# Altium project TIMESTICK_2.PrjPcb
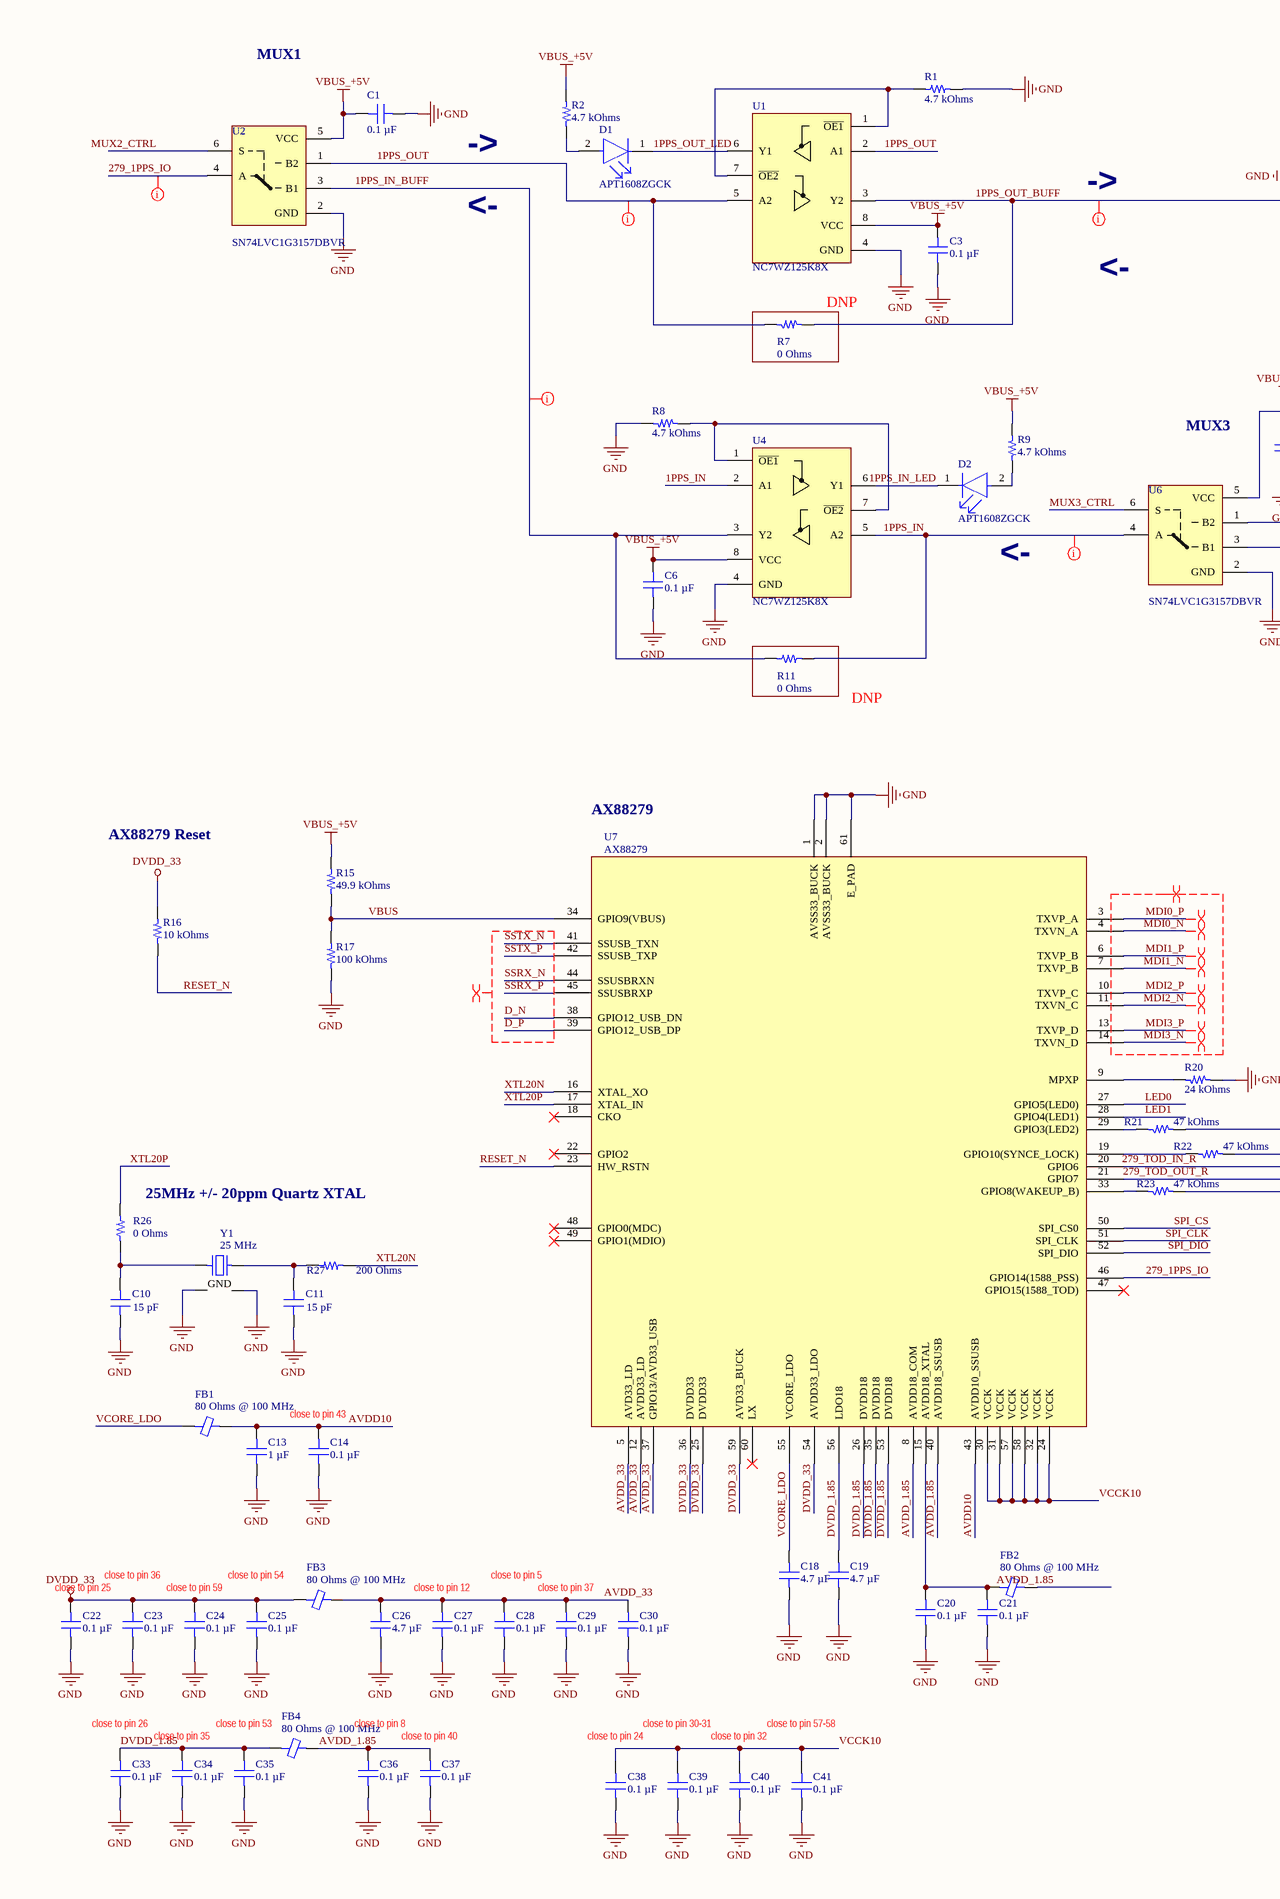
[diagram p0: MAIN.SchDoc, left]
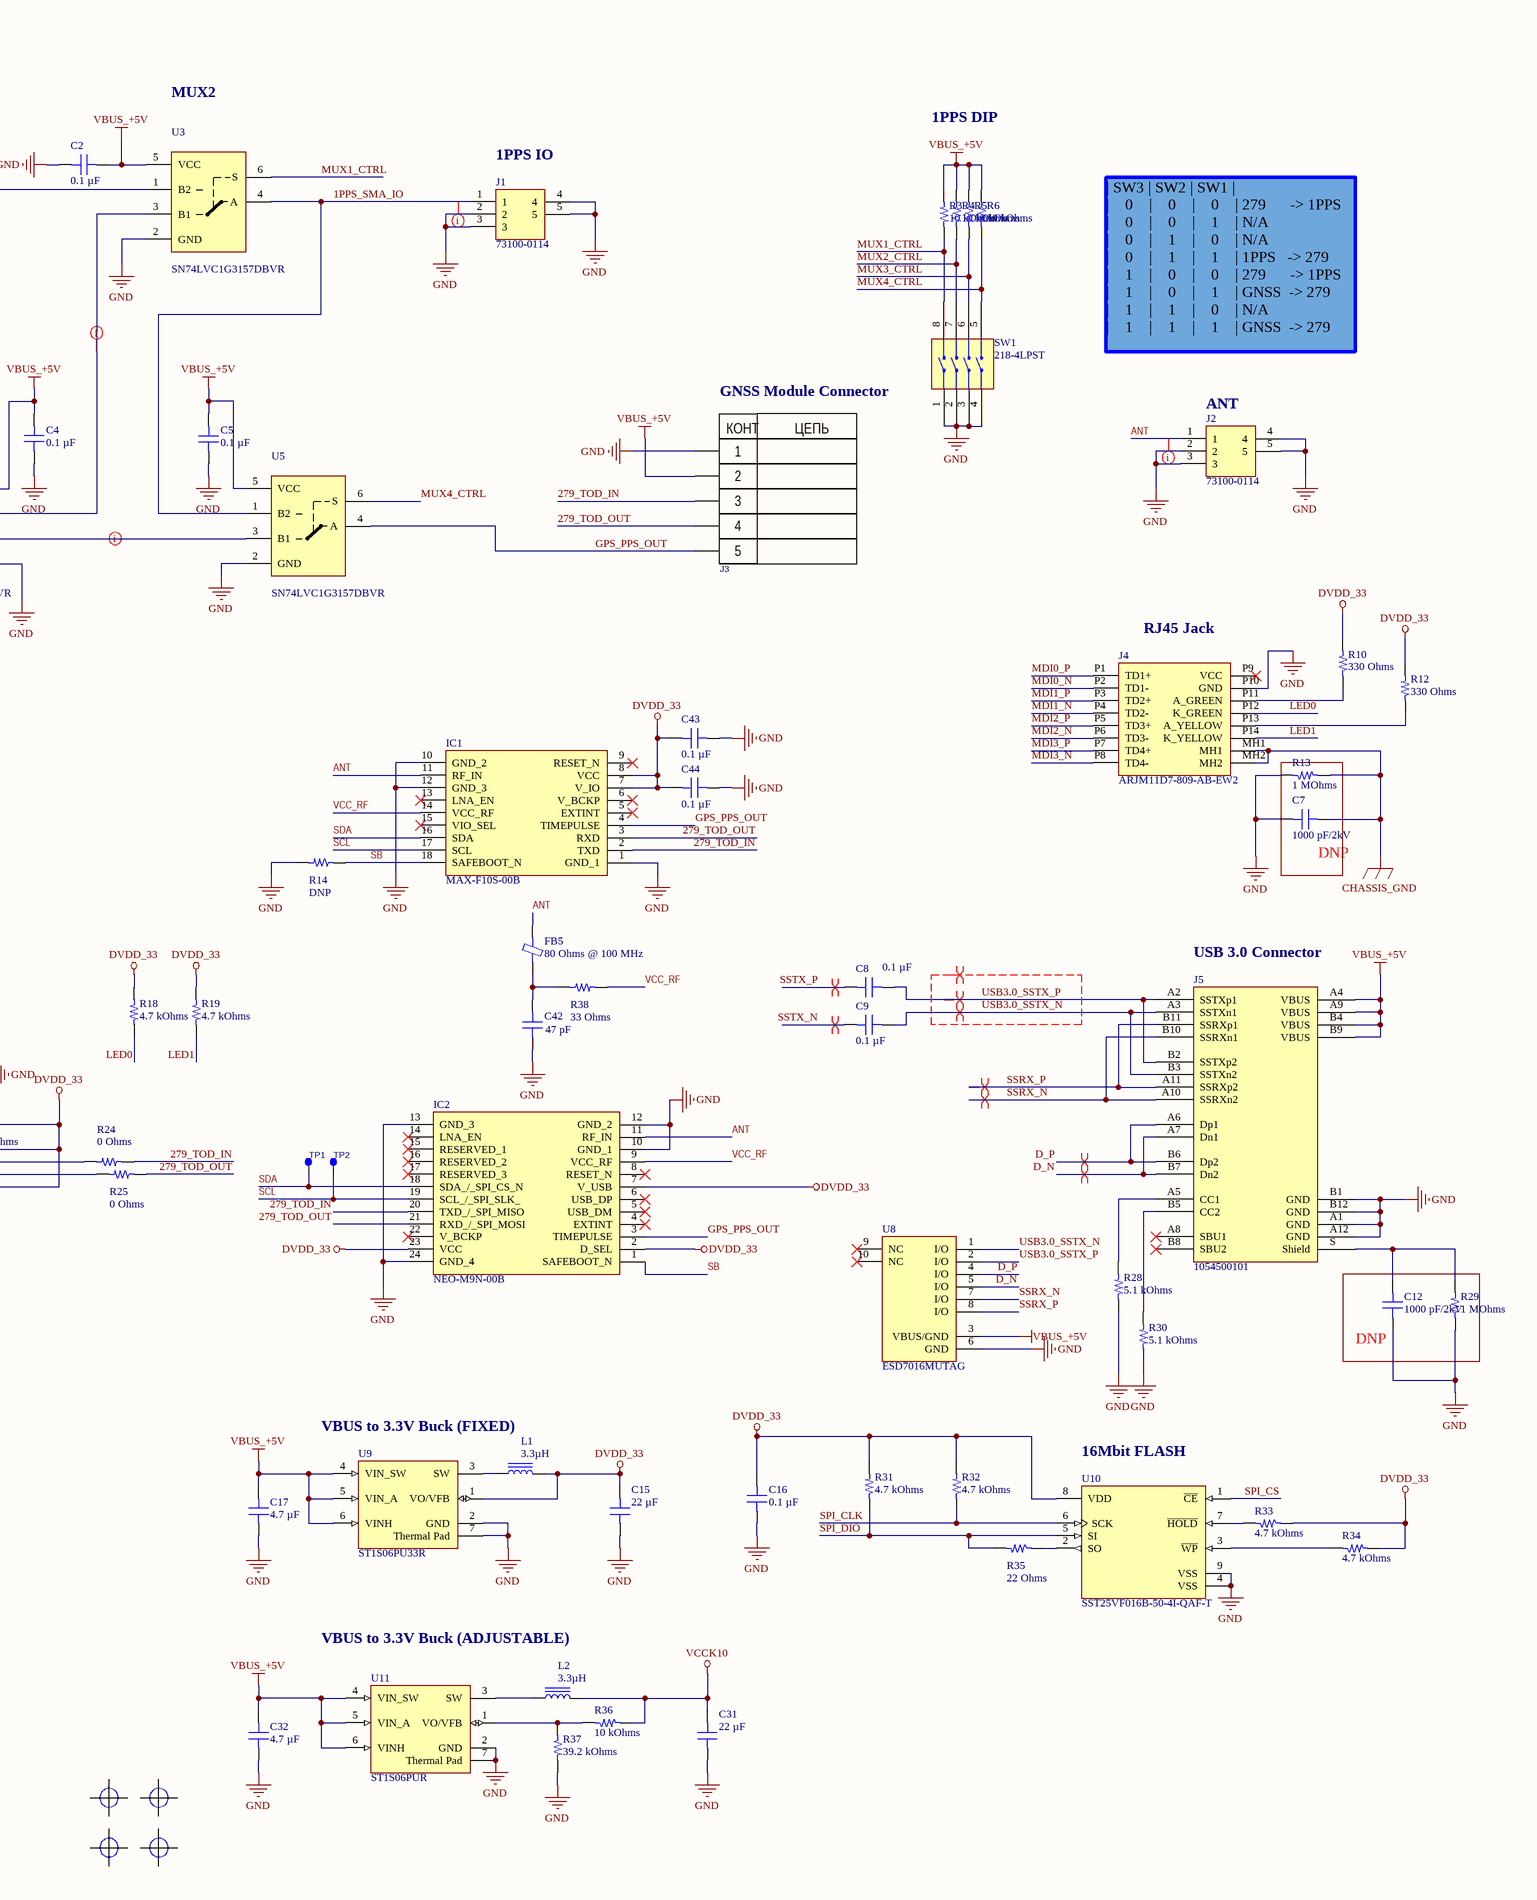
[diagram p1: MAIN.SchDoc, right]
1 sheet, 117 parts. Net scope: global (net labels, ports and power ports of the same name join across sheets).
Board file: TIMESTICK_2.PcbDoc

## Sheet MAIN.SchDoc
size A2; SheetNumber: 1; SheetTotal: 1

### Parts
C1  0.1 µF  [CAP 0402_1005]
C2  0.1 µF  [CAP 0402_1005]
C3  0.1 µF  [CAP 0402_1005]
C4  0.1 µF  [CAP 0402_1005]
C5  0.1 µF  [CAP 0402_1005]
C6  0.1 µF  [CAP 0402_1005]
C7  1000 pF/2kV  [CAP 1206_3216 - 0.8MM]
C8  0.1 µF  [CAP 0402_1005]
C9  0.1 µF  [CAP 0402_1005]
C10  15 pF  [CAP 0402_1005]
C11  15 pF  [CAP 0402_1005]
C12  1000 pF/2kV  [CAP 1206_3216 - 0.8MM]
C13  1 µF  [CAP 0402_1005]
C14  0.1 µF  [CAP 0402_1005]
C15  22 µF  [CAP 0603_1608]
C16  0.1 µF  [CAP 0402_1005]
C17  4.7 µF  [CAP 0402_1005]
C18  4.7 µF  [CAP 0402_1005]
C19  4.7 µF  [CAP 0402_1005]
C20  0.1 µF  [CAP 0402_1005]
C21  0.1 µF  [CAP 0402_1005]
C22  0.1 µF  [CAP 0402_1005]
C23  0.1 µF  [CAP 0402_1005]
C24  0.1 µF  [CAP 0402_1005]
C25  0.1 µF  [CAP 0402_1005]
C26  4.7 µF  [CAP 0402_1005]
C27  0.1 µF  [CAP 0402_1005]
C28  0.1 µF  [CAP 0402_1005]
C29  0.1 µF  [CAP 0402_1005]
C30  0.1 µF  [CAP 0402_1005]
C31  22 µF  [CAP 0603_1608]
C32  4.7 µF  [CAP 0402_1005]
C33  0.1 µF  [CAP 0402_1005]
C34  0.1 µF  [CAP 0402_1005]
C35  0.1 µF  [CAP 0402_1005]
C36  0.1 µF  [CAP 0402_1005]
C37  0.1 µF  [CAP 0402_1005]
C38  0.1 µF  [CAP 0402_1005]
C39  0.1 µF  [CAP 0402_1005]
C40  0.1 µF  [CAP 0402_1005]
C41  0.1 µF  [CAP 0402_1005]
C42  47 pF  [CAP 0402_1005]
C43  0.1 µF  [CAP 0402_1005]
C44  0.1 µF  [CAP 0402_1005]
D1  APT1608ZGCK  [FP-APT1608ZGCK-MFG]
D2  APT1608ZGCK  [FP-APT1608ZGCK-MFG]
FB1  80 Ohms @ 100 MHz  [FER 0402_1005]
FB2  80 Ohms @ 100 MHz  [FER 0402_1005]
FB3  80 Ohms @ 100 MHz  [FER 0402_1005]
FB4  80 Ohms @ 100 MHz  [FER 0402_1005]
FB5  80 Ohms @ 100 MHz  [FER 0402_1005]
IC1  MAX-F10S-00B  [MAXF10S00B]
IC2  NEO-M9N-00B  [NEOM9N00B]
J1  73100-0114  [731000114]
J2  73100-0114  [731000114]
J3  PBS-5  [PBS-5]  (value not drawn)
J4  ARJM11D7-809-AB-EW2  [ARJM11D7809ABEW2]
J5  1054500101  [Molex 1054500101]
L1  3.3µH  [IND 1008_2520]
L2  3.3µH  [IND 1008_2520]
MNT1  MOUNT_HOLE  [MOUNT_3mm]  (value not drawn)  (no BOM)
MNT2  MOUNT_HOLE  [MOUNT_3mm]  (value not drawn)  (no BOM)
MNT3  MOUNT_HOLE  [MOUNT_3mm]  (value not drawn)  (no BOM)
MNT4  MOUNT_HOLE  [MOUNT_3mm]  (value not drawn)  (no BOM)
R1  4.7 kOhms  [YAGEO RES 0402_1005]
R2  4.7 kOhms  [YAGEO RES 0402_1005]
R3  10 kOhms  [YAGEO RES 0402_1005]
R4  10 kOhms  [YAGEO RES 0402_1005]
R5  10 kOhms  [YAGEO RES 0402_1005]
R6  10 kOhms  [YAGEO RES 0402_1005]
R7  0 Ohms  [YAGEO RES 0402_1005]
R8  4.7 kOhms  [YAGEO RES 0402_1005]
R9  4.7 kOhms  [YAGEO RES 0402_1005]
R10  330 Ohms  [YAGEO RES 0402_1005]
R11  0 Ohms  [YAGEO RES 0402_1005]
R12  330 Ohms  [YAGEO RES 0402_1005]
R13  1 MOhms  [YAGEO RES 0402_1005]
R14  DNP  [YAGEO RES 0402_1005]
R15  49.9 kOhms  [YAGEO RES 0402_1005]
R16  10 kOhms  [YAGEO RES 0402_1005]
R17  100 kOhms  [YAGEO RES 0402_1005]
R18  4.7 kOhms  [YAGEO RES 0402_1005]
R19  4.7 kOhms  [YAGEO RES 0402_1005]
R20  24 kOhms  [YAGEO RES 0402_1005]
R21  47 kOhms  [YAGEO RES 0402_1005]
R22  47 kOhms  [YAGEO RES 0402_1005]
R23  47 kOhms  [YAGEO RES 0402_1005]
R24  0 Ohms  [YAGEO RES 0402_1005]
R25  0 Ohms  [YAGEO RES 0402_1005]
R26  0 Ohms  [YAGEO RES 0402_1005]
R27  200 Ohms  [YAGEO RES 0402_1005]
R28  5.1 kOhms  [YAGEO RES 0402_1005]
R29  1 MOhms  [YAGEO RES 0402_1005]
R30  5.1 kOhms  [YAGEO RES 0402_1005]
R31  4.7 kOhms  [YAGEO RES 0402_1005]
R32  4.7 kOhms  [YAGEO RES 0402_1005]
R33  4.7 kOhms  [YAGEO RES 0402_1005]
R34  4.7 kOhms  [YAGEO RES 0402_1005]
R35  22 Ohms  [YAGEO RES 0402_1005]
R36  10 kOhms  [YAGEO RES 0402_1005]
R37  39.2 kOhms  [YAGEO RES 0402_1005]
R38  33 Ohms  [YAGEO RES 0402_1005]
SW1  218-4LPST  [CTS 218-4LPJ]
TP1  PAD_TEST  [PAD_TEST]  (value not drawn)  (no BOM)
TP2  PAD_TEST  [PAD_TEST]  (value not drawn)  (no BOM)
U1  NC7WZ125K8X  [SOP50P310X90-8N]
U2  SN74LVC1G3157DBVR  [SOT95P280X145-6N]
U3  SN74LVC1G3157DBVR  [SOT95P280X145-6N]
U4  NC7WZ125K8X  [SOP50P310X90-8N]
U5  SN74LVC1G3157DBVR  [SOT95P280X145-6N]
U6  SN74LVC1G3157DBVR  [SOT95P280X145-6N]
U7  AX88279  [IC_AX88279]
U8  ESD7016MUTAG  [ONSC-UDFN-8-517CB_V]
U9  ST1S06PU33R  [DFN6D_L]
U10  SST25VF016B-50-4I-QAF-T  [FP-C04-452-MFG]
U11  ST1S06PUR  [DFN6D_M]
Y1  25 MHz  [NDK NX3225GA]

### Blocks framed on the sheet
DNP: R7
DNP: C7 R13
DNP: C12 R29

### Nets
CHASSIS_GND: C7.1 J4.MH1 J4.MH2 R13.1
DVDD_33: C15.2 C16.2 C22.2 C23.2 C24.2 C25.2 C43.2 C44.2 FB3.1 IC1.7(V_IO) IC1.8(VCC) IC2.2(D_SEL) IC2.7(V_USB) IC2.23(VCC) L1.2 R10.2 R12.2 R16.2 R18.1 R19.1 R21.2 R22.2 R23.2 R31.1 R32.1 R33.1 R34.1 U7.25(DVDD33) U7.36(DVDD33) U7.54(AVDD33_LDO) U7.59(AVD33_BUCK) U9.1(VO/VFB) U10.8(VDD)
GND: C1.1 C2.1 C3.1 C4.1 C5.1 C6.1 C7.2 C10.1 C11.1 C12.1 C13.1 C14.1 C15.1 C16.1 C17.1 C18.1 C19.1 C20.1 C21.1 C22.1 C23.1 C24.1 C25.1 C26.1 C27.1 C28.1 C29.1 C30.1 C31.1 C32.1 C33.1 C34.1 C35.1 C36.1 C37.1 C38.1 C39.1 C40.1 C41.1 C42.1 C43.1 C44.1 IC1.1(GND_1) IC1.10(GND_2) IC1.12(GND_3) IC2.10(GND_1) IC2.12(GND_2) IC2.13(GND_3) IC2.24(GND_4) J1.2 J1.3 J1.4 J1.5 J2.2 J2.3 J2.4 J2.5 J3.1 J4.P10(GND) J5.A1(GND) J5.A12(GND) J5.B1(GND) J5.B12(GND) R1.2 R8.1 R13.2 R14.2 R17.1 R20.1 R28.2 R29.1 R30.2 R37.2 SW1.1(GND) SW1.2(GND) SW1.3(GND) SW1.4(GND) U1.4(GND) U2.2(GND) U3.2(GND) U4.4(GND) U5.2(GND) U6.2(GND) U7.1(AVSS33_BUCK) U7.2(AVSS33_BUCK) U7.61(E_PAD) U8.6(GND) U9.2(GND) U9.7(Thermal_Pad) U10.4(VSS) U10.9(VSS) U11.2(GND) U11.7(Thermal_Pad) Y1.2(GND) Y1.4(GND)
VBUS_+5V: C1.2 C2.2 C3.2 C4.2 C5.2 C6.2 C17.2 C32.2 J3.2 J5.A4(VBUS) J5.A9(VBUS) J5.B4(VBUS) J5.B9(VBUS) R2.2 R3.2 R4.2 R5.2 R6.2 R9.2 R15.2 U1.8(VCC) U2.5(VCC) U3.5(VCC) U4.8(VCC) U5.5(VCC) U6.5(VCC) U8.3(VBUS/GND) U9.4(VIN_SW) U9.5(VIN_A) U9.6(VINH) U11.4(VIN_SW) U11.5(VIN_A) U11.6(VINH)
VCCK10: C31.2 C38.2 C39.2 C40.2 C41.2 L2.2 R36.1 U7.24(VCCK) U7.30(VCCK) U7.31(VCCK) U7.32(VCCK) U7.57(VCCK) U7.58(VCCK)
1PPS_IN: R11.1 U4.2(A1) U4.5(A2) U6.4(A)
1PPS_IN_BUFF: R11.2 U2.3(B1) U4.3(Y2)
1PPS_IN_LED: D2.1(C) U4.6(Y1)
1PPS_OUT: R7.2 U1.2(A1) U1.5(A2) U2.1(B2)
1PPS_OUT_BUFF: R7.1 U1.3(Y2) U3.1(B2)
1PPS_OUT_LED: D1.1(C) U1.6(Y1)
1PPS_SMA_IO: J1.1 U3.4(A) U5.1(B2)
279_1PPS_IO: U2.4(A) U7.46(GPIO14(1588_PSS))
279_TOD_IN: IC1.2(TXD) IC2.20(TXD_/_SPI_MISO) J3.3 R24.1
279_TOD_IN_R: R24.2 U7.20(GPIO6)
279_TOD_OUT: IC1.3(RXD) IC2.21(RXD_/_SPI_MOSI) J3.4 R25.1
279_TOD_OUT_R: R25.2 U7.21(GPIO7)
ANT: FB5.2 IC1.11(RF_IN) IC2.11(RF_IN) J2.1
AVDD10: C13.2 C14.2 FB1.2 U7.43(AVDD10_SSUSB)
AVDD_1.85: C36.2 C37.2 FB2.2 FB4.2 U7.8(AVDD18_COM) U7.40(AVDD18_SSUSB)
AVDD_33: C26.2 C27.2 C28.2 C29.2 C30.2 FB3.2 U7.5(AVD33_LD) U7.12(AVDD33_LD) U7.37(GPIO13/AVD33_USB)
D_N: J5.A7(Dn1) J5.B7(Dn2) U7.38(GPIO12_USB_DN) U8.5(I/O)
D_P: J5.A6(Dp1) J5.B6(Dp2) U7.39(GPIO12_USB_DP) U8.4(I/O)
DVDD_1.85: C19.2 C33.2 C34.2 C35.2 FB4.1 U7.26(DVDD18) U7.35(DVDD18) U7.53(DVDD18) U7.56(LDO18)
GPS_PPS_OUT: IC1.4(TIMEPULSE) IC2.3(TIMEPULSE) J3.5 U5.4(A)
LED0: J4.P12(K_GREEN) R18.2 U7.27(GPIO5(LED0))
LED1: J4.P14(K_YELLOW) R19.2 U7.28(GPIO4(LED1))
MDI0_N: J4.P2(TD1-) U7.4(TXVN_A)
MDI0_P: J4.P1(TD1+) U7.3(TXVP_A)
MDI1_N: J4.P4(TD2-) U7.7(TXVP_B)
MDI1_P: J4.P3(TD2+) U7.6(TXVP_B)
MDI2_N: J4.P6(TD3-) U7.11(TXVN_C)
MDI2_P: J4.P5(TD3+) U7.10(TXVP_C)
MDI3_N: J4.P8(TD4-) U7.14(TXVN_D)
MDI3_P: J4.P7(TD4+) U7.13(TXVP_D)
MUX1_CTRL: R3.1 SW1.8 U3.6(S)
MUX2_CTRL: R4.1 SW1.7 U2.6(S)
MUX3_CTRL: R5.1 SW1.6 U6.6(S)
MUX4_CTRL: R6.1 SW1.5 U5.6(S)
RESET_N: R16.1 U7.23(HW_RSTN)
SB: IC1.18(SAFEBOOT_N) IC2.1(SAFEBOOT_N) R14.1
SCL: IC1.17(SCL) IC2.19(SCL_/_SPI_SLK_) TP2.1
SDA: IC1.16(SDA) IC2.18(SDA_/_SPI_CS_N) TP1.1
SPI_CLK: R32.2 U7.51(SPI_CLK) U10.6(SCK)
SPI_CS: U7.50(SPI_CS0) U10.1(~{CE})
SPI_DIO: R31.2 R35.2 U7.52(SPI_DIO) U10.5(SI)
SSRX_N: J5.A10(SSRXn2) J5.B10(SSRXn1) U7.44(SSUSBRXN) U8.7(I/O)
SSRX_P: J5.A11(SSRXp2) J5.B11(SSRXp1) U7.45(SSUSBRXP) U8.8(I/O)
SSTX_N: C9.2 U7.41(SSUSB_TXN)
SSTX_P: C8.2 U7.42(SSUSB_TXP)
USB3.0_SSTX_N: C9.1 J5.A3(SSTXn1) J5.B3(SSTXn2) U8.1(I/O)
USB3.0_SSTX_P: C8.1 J5.A2(SSTXp1) J5.B2(SSTXp2) U8.2(I/O)
VBUS: R15.1 R17.2 U7.34(GPIO9(VBUS))
VCC_RF: IC1.14(VCC_RF) IC2.9(VCC_RF) R38.1
VCORE_LDO: C18.2 FB1.1 U7.55(VCORE_LDO)
XTL20N: R27.2 U7.16(XTAL_XO)
XTL20P: R26.2 U7.17(XTAL_IN)
NetC10_2: C10.2 R26.1 Y1.1
NetC11_2: C11.2 R27.1 Y1.3
NetC12_2: C12.2 J5.S(Shield) R29.2
NetC20_2: C20.2 C21.2 FB2.1 U7.15(AVDD18_XTAL)
NetC42_2: C42.2 FB5.1 R38.2
NetD1_2: D1.2(A) R2.1
NetD2_2: D2.2(A) R9.1
NetJ4_P11: J4.P11(A_GREEN) R10.1
NetJ4_P13: J4.P13(A_YELLOW) R12.1
NetJ5_A5: J5.A5(CC1) R28.1
NetJ5_B5: J5.B5(CC2) R30.1
NetL1_1: L1.1 U9.3(SW)
NetL2_1: L2.1 U11.3(SW)
NetR1_1: R1.1 U1.1(~{OE1}) U1.7(~{OE2})
NetR8_2: R8.2 U4.1(~{OE1}) U4.7(~{OE2})
NetR20_2: R20.2 U7.9(MPXP)
NetR21_1: R21.1 U7.29(GPIO3(LED2))
NetR22_1: R22.1 U7.19(GPIO10(SYNCE_LOCK))
NetR23_1: R23.1 U7.33(GPIO8(WAKEUP_B))
NetR33_2: R33.2 U10.7(~{HOLD})
NetR34_2: R34.2 U10.3(~{WP})
NetR35_1: R35.1 U10.2(SO)
NetR36_2: R36.2 R37.1 U11.1(VO/VFB)
NetU3_3: U3.3(B1) U6.1(B2)
NetU5_3: U5.3(B1) U6.3(B1)

Not connected (* = marked no-connect by the designer): IC1 5(EXTINT)* 6(V_BCKP)* 9(RESET_N)* 13(LNA_EN)* 15(VIO_SEL)*; IC2 4(EXTINT)* 5(USB_DM)* 6(USB_DP)* 8(RESET_N)* 14(LNA_EN)* 15(RESERVED_1)* 16(RESERVED_2)* 17(RESERVED_3)* 22(V_BCKP)*; J4 P9(VCC)*; J5 A8(SBU1)* B8(SBU2)*; U7 18(CKO)* 22(GPIO2)* 47(GPIO15(1588_TOD))* 48(GPIO0(MDC))* 49(GPIO1(MDIO))* 60(LX)*; U8 9(NC)* 10(NC)*

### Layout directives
differential pair; differential pair class MDI: MDI0_N, MDI0_P, MDI1_N, MDI1_P, MDI2_N, MDI2_P, MDI3_N, MDI3_P
differential pair; differential pair class USB; differential pair class *: D_N
differential pair; differential pair class USB: D_P, SSRX_N, SSRX_P, SSTX_N, SSTX_P, USB3.0_SSTX_N, USB3.0_SSTX_P
net class PPS_50: 1PPS_IN, 1PPS_IN_BUFF, 1PPS_OUT, 1PPS_OUT_BUFF, 1PPS_SMA_IO, 279_1PPS_IO, ANT, NetU3_3, NetU5_3
differential pair; differential pair class D100; net class MDI: MDI0_N, MDI0_P, MDI1_N, MDI1_P, MDI2_N, MDI2_P, MDI3_N, MDI3_P
differential pair; differential pair class D90; net class USB: D_N, D_P, SSRX_N, SSRX_P, SSTX_N, SSTX_P, USB3.0_SSTX_N, USB3.0_SSTX_P

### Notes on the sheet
- MUX1
- MUX2
- 1PPS DIP
- ->
- (near J1) 1PPS IO
- <-
- | SW3 | SW2 | SW1 |
  |    0    |    0    |    0    | 279      -> 1PPS
  |    0    |    0    |    1    | N/A
  |    0    |    1    |    0    | N/A
  |    0    |    1    |    1    | 1PPS   -> 279
  |    1    |    0    |    0    | 279      -> 1PPS
  |    1    |    0    |    1    | GNSS  -> 279
  |    1    |    1    |    0    | N/A
  |    1    |    1    |    1    | GNSS  -> 279
- MUX3
- GNSS Module Connector
- (near J2) ANT
- (near J4) RJ45 Jack
- DNP
- (near U7) AX88279
- AX88279 Reset
- (near J5) USB 3.0 Connector
- (near R26) 25MHz +/- 20ppm Quartz XTAL
- close to pin 43
- VBUS to 3.3V Buck (FIXED)
- (near U10) 16Mbit FLASH
- close to pin 36
- close to pin 54
- close to pin 5
- close to pin 25
- close to pin 59
- close to pin 12
- close to pin 37
- VBUS to 3.3V Buck (ADJUSTABLE)
- close to pin 26
- close to pin 35
- close to pin 53
- close to pin 8
- close to pin 40
- close to pin 24
- close to pin 30-31
- close to pin 32
- close to pin 57-58

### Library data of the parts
C1-C6 C8 C9 C14 C16 C20-C25 C27-C30 C33-C41 C43 C44 = CC0402KRX7R6BB104: CAP CER 0.1UF 10V X7R 0402; manufacturer: Yageo; Tolerance: ±10%
C7 C12 = CC1206KKX7RDBB102: CAP CER 1000PF 2KV X7R 1206; manufacturer: Yageo; Tolerance: ±10%; Voltage - Rated: 2000V (2kV)
C10 C11 = CC0402KRNPO9BN150: CAP CER 15PF 50V C0G/NPO 0402; manufacturer: Yageo; Tolerance: ±10%; Temperature Coefficient: C0G, NP0
C13 = CC0402KRX5R6BB105: CAP CER 1UF 10V X5R 0402; manufacturer: Yageo; Tolerance: ±10%
C15 C31 = CC0603MRX5R6BB226: CAP CER 22UF 10V X5R 0603; manufacturer: Yageo; Tolerance: ±20%
C17-C19 C26 C32 = CC0402MRX5R6BB475: CAP CER 4.7UF 10V X5R 0402; manufacturer: Yageo; Tolerance: ±20%
C42 = CC0402KRNPO9BN470: CAP CER 47PF 50V C0G/NPO 0402; manufacturer: Yageo; Tolerance: ±10%; Temperature Coefficient: C0G, NP0
D1 D2 = CMP-44529-000024-1: LED GREEN CLEAR CHIP SMD; Manufacturer: Kingbright; Forward Voltage: 3.3V; Dominant Wavelength: 525nm; Forward Current: 20mA; Lens Color: Colorless; Viewing Angle: 120°; Luminous Intensity: 350mcd
FB1-FB5 = BLM15PD800SN1D: FERRITE BEAD 80 OHM 0402 1LN; Manufacturer: Murata Electronics; Number of Lines: 1; Current Rating (Max): 1.5A; DC Resistance (DCR) (Max): 70mOhm; Filter Type: Power Line
IC1 = MAX-F10S-00B: Integrated Circuit; Manufacturer_Name: u-blox
IC2 = NEO-M9N-00B: Integrated Circuit; Manufacturer_Name: u-blox
J1 J2 = 73100-0114: Connector; Manufacturer_Name: Molex
J3 = PBS-5: Connector; Manufacturer: Connfly; Part Number: PBD-5; Part Number1: DS-1023-1x5
J4 = ARJM11D7-809-AB-EW2: Connector; Manufacturer_Name: ABRACON
J5 = 1054500101: CONN RCP USB3.1 TYPEC 24P SMD RA; Manufacturer: Molex; Connector Type: USB - C (Type - C); Current Rating (Amps): 0.25A, 1A, 5A; Gender: Receptacle; Mating Cycles: 10000; Number of Contacts: 24; Number of Ports: 1; Shielding: Shielded; Specifications: USB 3.1 (USB 3.1 Gen 2, Superspeed+); Voltage - Rated: 30VAC/DC
L1 L2 = LQM2HPN3R3MG0L: FIXED IND 3.3UH 1.2A 100 MOHM; Manufacturer: Murata Electronics; Shielding: Shielded; Tolerance: ±20%; DC Resistance (DCR): 125mOhm Max; Frequency - Self Resonant: 30MHz; Inductance Frequency - Test: 1MHz; Material - Core: Ferrite; Type: Multilayer
MNT1-MNT4 = MOUNT_HOLE: Mount hole
R1 R2 R8 R9 R18 R19 R31-R34 = RC0402FR-074k7L: RES 4.7K OHM 1% 1/16W 0402; Manufacturer: Yageo; Power (Watts): 0.063W, 1/16W; Temperature Coefficient: ±100ppm/°C
R3-R6 R16 R36 = RC0402FR-0710KL: RES 10K OHM 1% 1/16W 0402; Manufacturer: Yageo; Power (Watts): 0.063W, 1/16W; Temperature Coefficient: ±100ppm/°C
R7 R11 R24-R26 = RC0402FR-070RL: RES 0 OHM JUMPER 1/16W 0402; Manufacturer: Yageo; Power (Watts): 0.063W, 1/16W
R10 R12 = RC0402FR-07330RL: RES 330 OHM 1% 1/16W 0402; Manufacturer: Yageo; Power (Watts): 0.063W, 1/16W; Temperature Coefficient: ±100ppm/°C
R13 R29 = RC0402FR-071ML: RES 1M OHM 1% 1/16W 0402; Manufacturer: Yageo; Power (Watts): 0.063W, 1/16W; Temperature Coefficient: ±100ppm/°C
R14 = RC0402FR-070RL: RES 0 OHM JUMPER 1/16W 0402; Manufacturer: Yageo; Resistance: 0 Ohms; Value: 0 Ohms; Power (Watts): 0.063W, 1/16W
R15 = RC0402FR-0749K9L: RES 49.9K OHM 1% 1/16W 0402; Manufacturer: Yageo; Power (Watts): 0.063W, 1/16W; Temperature Coefficient: ±100ppm/°C
R17 = RC0402FR-07100KL: RES 100K OHM 1% 1/16W 0402; Manufacturer: Yageo; Power (Watts): 0.063W, 1/16W; Temperature Coefficient: ±100ppm/°C
R20 = RC0402FR-0724KL: RES 24K OHM 1% 1/16W 0402; Manufacturer: Yageo; Power (Watts): 0.063W, 1/16W; Temperature Coefficient: ±100ppm/°C
R21-R23 = RC0402FR-0747KL: RES 47K OHM 1% 1/16W 0402; Manufacturer: Yageo; Power (Watts): 0.063W, 1/16W; Temperature Coefficient: ±100ppm/°C
R27 = RC0402FR-07200RL: RES 200 OHM 1% 1/16W 0402; Manufacturer: Yageo; Temperature Coefficient: ±100ppm/°C; Power (Watts): 0.063W, 1/16W
R28 R30 = RC0402FR-075k1L: RES 5.1K OHM 1% 1/16W 0402; Manufacturer: Yageo; Power (Watts): 0.063W, 1/16W; Temperature Coefficient: ±100ppm/°C
R35 = RC0402FR-0722RL: RES 22 OHM 1% 1/16W 0402; Manufacturer: Yageo; Power (Watts): 0.063W, 1/16W; Temperature Coefficient: ±100ppm/°C
R37 = RC0402FR-0739K2L: RES 39.2K OHM 1% 1/16W 0402; Manufacturer: Yageo; Power (Watts): 0.063W, 1/16W; Temperature Coefficient: ±100ppm/°C
R38 = RC0402FR-0733RL: RES 33 OHM 1% 1/16W 0402; Manufacturer: Yageo; Power (Watts): 0.063W, 1/16W; Temperature Coefficient: ±100ppm/°C
SW1 = 218-4LPST: SWITCH SLIDE DIP SPST 25MA 24V; Manufacturer: CTS Electrocomponents; Actuator Level: Flush, Recessed; Actuator Type: Slide (Standard); Number of Positions: 4; Pitch: 0.050" (1.27mm), Half; Voltage Rating: 24VDC; Washable: Yes
TP1 TP2 = PAD_TEST: Test Point; Manufacturer: {Manufacturer}; Reseller3: {Reseller3}; Reseller1: {Reseller1}; Tempcoeff: {Tempcoeff}; Reseller2: {Reseller2}; Tolerance: {Tolerance}; Value: .NetName; PowerVoltage: {PowerVoltage}; CatalogueCode: {CatalogueCode}
U1 U4 = NC7WZ125K8X: Integrated Circuit; Manufacturer_Name: onsemi
U2 U3 U5 U6 = SN74LVC1G3157DBVR: Integrated Circuit; Manufacturer_Name: Texas Instruments
U7 = IC_AX88279
U8 = CMP-1063-00263-1: Low Capacitance ESD Protection USB 3.0, 8-Pin UDFN, Pb-Free, Tape and Reel; Manufacturer: On Semiconductor; V(BR) Min (V): 5.5; Direction: Bidirectional; VRWM Max (V): 5; Number of Lines: 6; C Max (pF): 0.2; IR Max (uA): 1
U9 = CMP-0240-00158-1: Synchronous rectification with inhibit, 1.5 A, 1.5 MHz adjustable, step-down switching regulator, 6-Pin DFN; Manufacturer: STMicroelectronics; Min Input Voltage: 2.7V; Number of Outputs: 1; Output Current: 1.5A; Output Voltage: 3.3V; Max Supply Voltage: 6V; Switching Frequency: 1.5MHz; Output Type: Fixed,Adjustable; Quiescent Current: 1.5mA; Efficiency: 90%; Synchronous Rectifier: Yes; Polarity: Positive; Accuracy: 2%
U10 = CMP-00252-18686437-1: SST25VF016B-50-4I-QAF-T Flash Serial-SPI 3.3V 16Mbit 2M x 8bit 8ns 8-Pin WSON EP T/R - Tape and Reel; Max Supply Voltage: 3.6V; Density: 16Mb; Interface: SPI; Memory Size: 2MB; Data Bus Width: 8b; Max Frequency: 50MHz; Nominal Supply Current: 15mA; Address Bus Width: 1b; Min Supply Voltage: 2.7V; Sync/Async: Synchronous
U11 = CMP-0240-00159-1: Synchronous rectification with inhibit, 1.5 A, 1.5 MHz adjustable, step-down switching regulator, 6-Pin DFN
Y1 = NX3225GA-25.000M-STD-CRG-2: CRYSTAL 25.0000MHZ 8PF SMD; Manufacturer: NDK America, Inc.; Frequency Stability: ±30ppm; Frequency Tolerance: ±20ppm; ESR (Equivalent Series Resistance): 50 Ohms; Operating Mode: Fundamental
